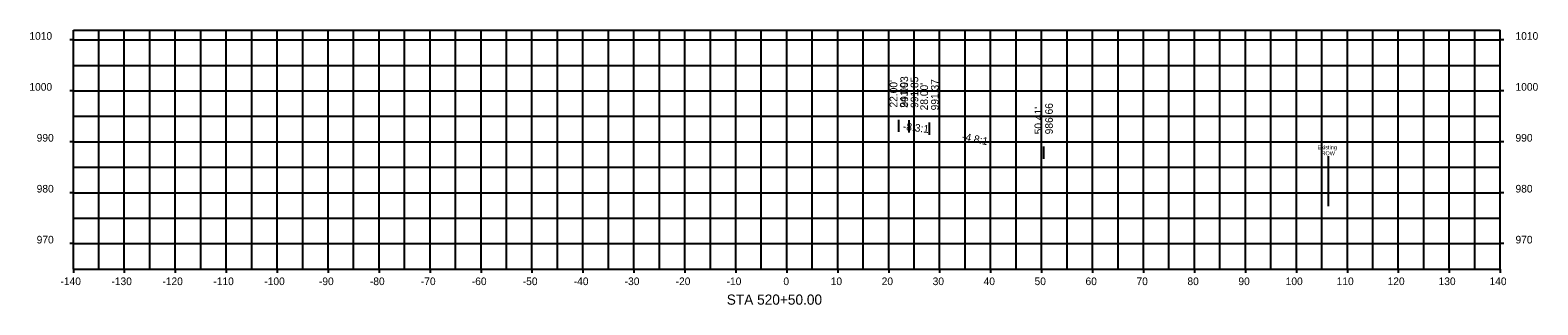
# Model space of a CAD drawing. Extents: x -148 to 147, y 958 to 1012.
import ezdxf

# ---------------------------------------------------------------- set-up
doc = ezdxf.new("R2010")
doc.units = 0
for name, color, linetype in [('ROW', 7, 'Continuous'), ('SheetBorder', 7, 'Continuous'), ('SheetGridMajor', 7, 'Continuous'), ('SheetGridMinor', 7, 'Continuous'), ('SheetText', 7, 'Continuous'), ('Text', 7, 'Continuous')]:
    doc.layers.add(name, color=color, linetype=linetype)

msp = doc.modelspace()

# ---------------------------------------------------------------- linework, layer by layer
at = {"layer": 'ROW'}
msp.add_line((106.24, 987.18), (106.24, 977.34), dxfattribs=at)
at = {"layer": 'SheetBorder'}
for p, q in [((-140, 1011.93), (140, 1011.93)), ((-140, 965), (-140, 1011.93)), ((140, 965), (140, 1011.93)), ((-140, 965), (140, 965))]:
    msp.add_line(p, q, dxfattribs=at)
at = {"layer": 'SheetGridMajor'}
for p, q in [((-130, 965), (-130, 1011.93)), ((-120, 965), (-120, 1011.93)), ((-110, 965), (-110, 1011.93)), ((-100, 965), (-100, 1011.93)), ((-90, 965), (-90, 1011.93)), ((-80, 965), (-80, 1011.93)), ((-70, 965), (-70, 1011.93)), ((-60, 965), (-60, 1011.93)), ((-50, 965), (-50, 1011.93)), ((-40, 965), (-40, 1011.93)), ((-30, 965), (-30, 1011.93)), ((-20, 965), (-20, 1011.93)), ((-10, 965), (-10, 1011.93)), ((0, 965), (0, 1011.93)), ((10, 965), (10, 1011.93)), ((20, 965), (20, 1011.93)), ((30, 965), (30, 1011.93)), ((40, 965), (40, 1011.93)), ((50, 965), (50, 1011.93)), ((60, 965), (60, 1011.93)), ((70, 965), (70, 1011.93)), ((80, 965), (80, 1011.93)), ((90, 965), (90, 1011.93)), ((100, 965), (100, 1011.93)), ((110, 965), (110, 1011.93)), ((120, 965), (120, 1011.93)), ((130, 965), (130, 1011.93)), ((-140, 1010), (-140.72, 1010)), ((-140, 1010), (140, 1010)), ((140.72, 1010), (140, 1010)), ((-140, 1000), (-140.72, 1000)), ((-140, 1000), (140, 1000)), ((140.72, 1000), (140, 1000)), ((-140, 990), (-140.72, 990)), ((-140, 990), (140, 990)), ((140.72, 990), (140, 990)), ((-140, 980), (-140.72, 980)), ((-140, 980), (140, 980)), ((140.72, 980), (140, 980)), ((-140, 970), (-140.72, 970)), ((-140, 970), (140, 970)), ((140.72, 970), (140, 970)), ((-140, 965), (-140, 964.28)), ((-130, 965), (-130, 964.28)), ((-120, 965), (-120, 964.28)), ((-110, 965), (-110, 964.28)), ((-100, 965), (-100, 964.28)), ((-90, 965), (-90, 964.28)), ((-80, 965), (-80, 964.28)), ((-70, 965), (-70, 964.28)), ((-60, 965), (-60, 964.28)), ((-50, 965), (-50, 964.28)), ((-40, 965), (-40, 964.28)), ((-30, 965), (-30, 964.28)), ((-20, 965), (-20, 964.28)), ((-10, 965), (-10, 964.28)), ((0, 965), (0, 964.28)), ((10, 965), (10, 964.28)), ((20, 965), (20, 964.28)), ((30, 965), (30, 964.28)), ((40, 965), (40, 964.28)), ((50, 965), (50, 964.28)), ((60, 965), (60, 964.28)), ((70, 965), (70, 964.28)), ((80, 965), (80, 964.28)), ((90, 965), (90, 964.28)), ((100, 965), (100, 964.28)), ((110, 965), (110, 964.28)), ((120, 965), (120, 964.28)), ((130, 965), (130, 964.28)), ((140, 965), (140, 964.28))]:
    msp.add_line(p, q, dxfattribs=at)
at = {"layer": 'SheetGridMinor'}
for p, q in [((-135, 965), (-135, 1011.93)), ((-125, 965), (-125, 1011.93)), ((-115, 965), (-115, 1011.93)), ((-105, 965), (-105, 1011.93)), ((-95, 965), (-95, 1011.93)), ((-85, 965), (-85, 1011.93)), ((-75, 965), (-75, 1011.93)), ((-65, 965), (-65, 1011.93)), ((-55, 965), (-55, 1011.93)), ((-45, 965), (-45, 1011.93)), ((-35, 965), (-35, 1011.93)), ((-25, 965), (-25, 1011.93)), ((-15, 965), (-15, 1011.93)), ((-5, 965), (-5, 1011.93)), ((5, 965), (5, 1011.93)), ((15, 965), (15, 1011.93)), ((25, 965), (25, 1011.93)), ((35, 965), (35, 1011.93)), ((45, 965), (45, 1011.93)), ((55, 965), (55, 1011.93)), ((65, 965), (65, 1011.93)), ((75, 965), (75, 1011.93)), ((85, 965), (85, 1011.93)), ((95, 965), (95, 1011.93)), ((105, 965), (105, 1011.93)), ((115, 965), (115, 1011.93)), ((125, 965), (125, 1011.93)), ((135, 965), (135, 1011.93)), ((-140, 1005), (140, 1005)), ((-140, 995), (140, 995)), ((-140, 985), (140, 985)), ((-140, 975), (140, 975))]:
    msp.add_line(p, q, dxfattribs=at)
at = {"layer": 'Text'}
for p, q in [((22, 991.93), (22, 994.33)), ((24, 991.85), (24, 994.25)), ((28, 991.37), (28, 993.77)), ((50.41, 986.66), (50.41, 989.06))]:
    msp.add_line(p, q, dxfattribs=at)

# ---------------------------------------------------------------- texts
at = {"layer": 'ROW'}
for s, p in [('Existing', (104.15, 988.53)), ('ROW', (104.92, 987.35))]:
    msp.add_text(s, height=0.787, dxfattribs=at).set_placement(p)
at = {"layer": 'SheetText'}
for s, height, p in [('1010', 1.5, (-148.63, 1010.03)), ('1010', 1.5, (143, 1010.03)), ('1000', 1.5, (-148.63, 1000.03)), ('1000', 1.5, (143, 1000.03)), ('990', 1.5, (-147.2, 990.03)), ('990', 1.5, (143, 990.03)), ('980', 1.5, (-147.2, 980.03)), ('980', 1.5, (143, 980.03)), ('970', 1.5, (-147.2, 970.03)), ('970', 1.5, (143, 970.03)), ('-140', 1.5, (-142.53, 961.85)), ('-130', 1.5, (-132.53, 961.85)), ('-120', 1.5, (-122.53, 961.85)), ('-110', 1.5, (-112.53, 961.85)), ('-100', 1.5, (-102.53, 961.85)), ('-90', 1.5, (-91.81, 961.85)), ('-80', 1.5, (-81.81, 961.85)), ('-70', 1.5, (-71.81, 961.85)), ('-60', 1.5, (-61.81, 961.85)), ('-50', 1.5, (-51.81, 961.85)), ('-40', 1.5, (-41.81, 961.85)), ('-30', 1.5, (-31.81, 961.85)), ('-20', 1.5, (-21.81, 961.85)), ('-10', 1.5, (-11.81, 961.85)), ('0', 1.5, (-0.67, 961.85)), ('10', 1.5, (8.62, 961.85)), ('20', 1.5, (18.62, 961.85)), ('30', 1.5, (28.62, 961.85)), ('40', 1.5, (38.62, 961.85)), ('50', 1.5, (48.62, 961.85)), ('60', 1.5, (58.62, 961.85)), ('70', 1.5, (68.62, 961.85)), ('80', 1.5, (78.62, 961.85)), ('90', 1.5, (88.62, 961.85)), ('100', 1.5, (97.9, 961.85)), ('110', 1.5, (107.9, 961.85)), ('120', 1.5, (117.9, 961.85)), ('130', 1.5, (127.9, 961.85)), ('140', 1.5, (137.9, 961.85)), ('STA 520+50.00', 2.004, (-11.78, 958))]:
    msp.add_text(s, height=height, dxfattribs=at).set_placement(p)
at = {"layer": 'Text'}
for s, rotation, p in [("22.00'", 90, (21.7, 996.73)), ("24.00'", 90, (23.7, 996.65)), ('991.93', 90, (23.8, 996.73)), ('991.85', 90, (25.8, 996.65)), ("28.00'", 90, (27.7, 996.17)), ('991.37', 90, (29.8, 996.17)), ('986.66', 90, (52.21, 991.46)), ("50.41'", 90, (50.11, 991.46)), ('-8.3:1', 353.1572, (22.72, 992.33)), ('-4.8:1', 348.1402, (34.29, 990.37))]:
    msp.add_text(s, height=1.5, rotation=rotation, dxfattribs=at).set_placement(p)

doc.saveas('drawing.dxf')
